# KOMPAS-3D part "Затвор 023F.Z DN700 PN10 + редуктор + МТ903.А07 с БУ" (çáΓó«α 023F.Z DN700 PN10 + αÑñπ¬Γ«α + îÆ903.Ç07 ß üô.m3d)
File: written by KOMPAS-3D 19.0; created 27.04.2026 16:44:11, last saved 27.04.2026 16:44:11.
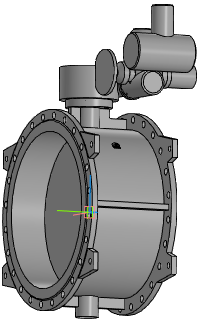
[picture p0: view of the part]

Document properties: Полное имя файла: ..\..\Затвор 023F.Z DN400-DN1600 + редуктор + МТ903\Затвор 023F.Z DN700 PN10 + редуктор + МТ903.А07 с БУ.a3d

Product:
- Part/product: Затвор 023F.Z DN700 PN10 + редуктор + МТ903.А07 с БУ
    Масса: 675.192

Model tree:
1. Операция без истории:1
